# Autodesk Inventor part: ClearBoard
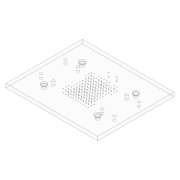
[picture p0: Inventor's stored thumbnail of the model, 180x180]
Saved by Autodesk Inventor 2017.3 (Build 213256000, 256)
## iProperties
Part Number: ClearBoard
Material: PET プラスチック
Document SubType Name: Modeling
Designer: kyushu-hep
Density: 1.541 g/cm^3
Appearance: ポリカーボネート - クリア
Author: kyushu-hep
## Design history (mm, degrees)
sketch "スケッチ1"
  geometry: L1 (60, -50)-(-60, -50); L2 (-60, -50)-(-60, 50); L3 (-60, 50)-(60, 50); L4 (60, 50)-(60, -50); L5 (60, -50)-(-60, 50); L6 (-60, -50)-(60, 50); 1 further point
  constraints: 12 end point, 2 midpoint, 2 parallel, 1 horizontal, 1 perpendicular
  dimensions: "d0" = 120 distance of L2.end L3.end; "d1" = 100 distance of L1.end L2.end
extrude "押し出し1" new body sketch "スケッチ1" distance "d2" = 5; taper "d3" = 0 deg
sketch "スケッチ2"
  geometry: L1 (-100, 50)-(-100, -50); L2 (-100, -50)-(100, -50); C1 r 0.75 at (-5.05, 29.5); C2 r 0.75 at (5.05, 29.5); 2 further points
  constraints: 4 end point, 2 centre point
  dimensions: "d4" = 1.5 diameter of C1; "d5" = 1.5 diameter of C2; "d6" = 10.1 distance of C2.centre C1.centre; "d7" = 29.5 vertical distance of point (0, 0) C2.centre; "d8" = 5.05 horizontal distance of C1.centre point (0, 0)
extrude "押し出し2" cut sketch "スケッチ2" distance "d9" = 5; taper "d10" = 0 deg
sketch "スケッチ3"
  geometry: C1 r 2.5 at (-35, 25); C2 r 2.5 at (35, 25); C3 r 2.5 at (-35, -25); C4 r 2.5 at (35, -25); 1 further point
  constraints: 4 centre point
  dimensions: "d11" = 5 diameter of C1; "d14" = 25 vertical distance of C1.centre point (0, 0); "d15" = 35 horizontal distance of C1.centre point (0, 0); "d18" = 5 diameter of C2; "d19" = 35 horizontal distance of point (0, 0) C2.centre; "d20" = 25 vertical distance of C2.centre point (0, 0); "d21" = 5 diameter of C3; "d22" = 25 vertical distance of point (0, 0) C3.centre; "d23" = 35 horizontal distance of point (0, 0) C3.centre; "d24" = 5 diameter of C4; "d25" = 25 vertical distance of point (0, 0) C4.centre; "d26" = 35 horizontal distance of point (0, 0) C4.centre
extrude "押し出し3" cut sketch "スケッチ3" distance "d27" = 5; taper "d28" = 0 deg
sketch "スケッチ5"
  geometry: L1 (17.5, -19.5)-(-17.5, -19.5); L2 (-17.5, -19.5)-(-17.5, 19.5); L3 (-17.5, 19.5)-(17.5, 19.5); L4 (17.5, 19.5)-(17.5, -19.5); L5 (17.5, -19.5)-(-17.5, 19.5); L6 (-17.5, -19.5)-(17.5, 19.5); C1 r 0.5 at (-16.5, 18.5); C2 r 0.5 at (-13.2, 18.5); C3 r 0.5 at (-9.9, 18.5); C4 r 0.5 at (-6.6, 18.5); C5 r 0.5 at (-3.3, 18.5); C6 r 0.5 at (0, 18.5); C7 r 0.5 at (3.3, 18.5); C8 r 0.5 at (6.6, 18.5); C9 r 0.5 at (9.9, 18.5); C10 r 0.5 at (13.2, 18.5); C11 r 0.5 at (-16.5, 14.8); C12 r 0.5 at (-13.2, 14.8); C13 r 0.5 at (-9.9, 14.8); C14 r 0.5 at (-6.6, 14.8); C15 r 0.5 at (-3.3, 14.8); C16 r 0.5 at (0, 14.8); C17 r 0.5 at (3.3, 14.8); C18 r 0.5 at (6.6, 14.8); C19 r 0.5 at (9.9, 14.8); C20 r 0.5 at (13.2, 14.8); C21 r 0.5 at (16.5, 18.5); C22 r 0.5 at (16.5, 14.8); C23 r 0.5 at (-16.5, 11.1); C24 r 0.5 at (-13.2, 11.1); C25 r 0.5 at (-9.9, 11.1); C26 r 0.5 at (-6.6, 11.1); C27 r 0.5 at (-3.3, 11.1); C28 r 0.5 at (0, 11.1); C29 r 0.5 at (3.3, 11.1); C30 r 0.5 at (6.6, 11.1); C31 r 0.5 at (9.9, 11.1); C32 r 0.5 at (13.2, 11.1); C33 r 0.5 at (16.5, 11.1); C34 r 0.5 at (-16.5, 7.4); C35 r 0.5 at (-13.2, 7.4); C36 r 0.5 at (-9.9, 7.4); C37 r 0.5 at (-6.6, 7.4); C38 r 0.5 at (-3.3, 7.4); C39 r 0.5 at (0, 7.4); C40 r 0.5 at (3.3, 7.4); C41 r 0.5 at (6.6, 7.4); C42 r 0.5 at (9.9, 7.4); C43 r 0.5 at (13.2, 7.4); C44 r 0.5 at (16.5, 7.4); C45 r 0.5 at (-16.5, 3.7); C46 r 0.5 at (-13.2, 3.7); C47 r 0.5 at (-9.9, 3.7); C48 r 0.5 at (-6.6, 3.7); C49 r 0.5 at (-3.3, 3.7); C50 r 0.5 at (0, 3.7); C51 r 0.5 at (3.3, 3.7); C52 r 0.5 at (6.6, 3.7); C53 r 0.5 at (9.9, 3.7); C54 r 0.5 at (13.2, 3.7); C55 r 0.5 at (16.5, 3.7); C56 r 0.5 at (-16.5, 0); C57 r 0.5 at (-13.2, 0); C58 r 0.5 at (-9.9, 0); C59 r 0.5 at (-6.6, 0); C60 r 0.5 at (-3.3, 0); C61 r 0.5 at (0, 0); C62 r 0.5 at (3.3, 0); C63 r 0.5 at (6.6, 0); C64 r 0.5 at (9.9, 0)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; 1 further point
  constraints: 121 centre point, 12 end point, 2 horizontal, 2 midpoint, 2 parallel, 1 perpendicular, 1 vertical, 240 other
  dimensions: "d58" = 35 distance of L2.end L3.end; "d59" = 39 distance of L3.end L1.start; "d60" = 1 diameter of C1; "d61" = 16.5 horizontal distance of point (0, 0) C1.centre; "d62" = 18.5 vertical distance of point (0, 0) C1.centre; "d65" = 3.3 distance of C1.centre C2.centre; "d68" = 3.7 distance of C1.centre C11.centre
extrude "押し出し10" cut sketch "スケッチ5" distance "d89" = 10; taper "d90" = 0 deg
sketch "スケッチ7"
  geometry: L1 (20, 20)-(-20, 20); L2 (-20, 20)-(-20, -20); L3 (-20, -20)-(20, -20); L4 (20, -20)-(20, 20); L5 (20, 20)-(-20, -20); L6 (-20, 20)-(20, -20); C1 r 1.75 at (-48, -16); C2 r 1.75 at (-48, 16); C3 r 1.75 at (-32, -16); C4 r 1.75 at (-32, 16); C5 r 1.75 at (-16, -16); C6 r 1.75 at (-16, 16); C7 r 1.75 at (0, -16); C8 r 1.75 at (0, 16); C9 r 1.75 at (16, -16); C10 r 1.75 at (16, 16); C11 r 1.75 at (32, -16); C12 r 1.75 at (32, 16); C13 r 1.75 at (48, -16); C14 r 1.75 at (48, 16); 2 further points
  constraints: 14 centre point, 12 end point, 2 horizontal, 2 midpoint, 2 parallel, 1 perpendicular, 1 vertical, 26 other
  dimensions: "d95" = 3.5 diameter of C1; "d96" = 48 horizontal distance of point (0, 0) C1.centre; "d97" = 16 vertical distance of point (0, 0) C1.centre; "d98" = 40 distance of L3.end L2.end; "d99" = 40 distance of L2.end L1.end; "d100" = 32 distance of C1.centre C2.centre; "d101" = 16 distance of C1.centre C3.centre
extrude "押し出し11" cut sketch "スケッチ7" distance "d102" = 5; taper "d103" = 0 deg
sketch "スケッチ9"
  geometry: C1 r 2.5 at (35, -25); C2 r 3.5 at (35, -25); C3 r 2.5 at (-35, -25); C4 r 3.5 at (-35, -25); C5 r 2.5 at (35, 25); C6 r 3.5 at (35, 25); C7 r 3.5 at (-35, 25); 2 further points
  constraints: 7 centre point, 3 coincident
  dimensions: "d110" = 7 diameter of C2; "d111" = 7 diameter of C4; "d112" = 7 diameter of C6; "d113" = 7 diameter of C7
extrude "押し出し13" cut sketch "スケッチ9" distance "d114" = 2; taper "d115" = 0 deg
node "ソリッド1"
